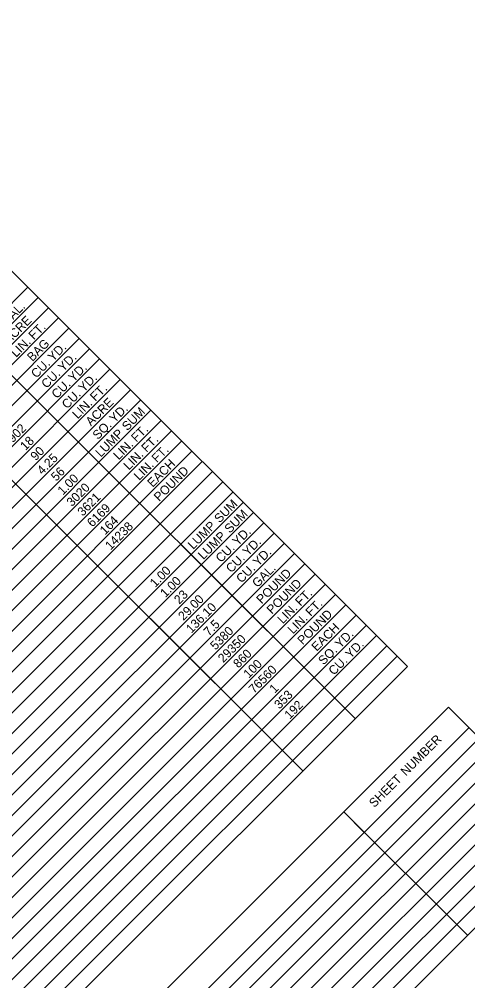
# Model space of a CAD drawing. Extents: x 1675667 to 1681231, y 227227 to 232694.
# Drawn here: x 1680479 to 1680780, y 231542 to 232189 of the extents above; entities that cross this region are included whole.
import ezdxf

# ---------------------------------------------------------------- set-up
doc = ezdxf.new("R2010")
doc.units = 0
doc.layers.add('Default', color=7, linetype='Continuous')

msp = doc.modelspace()

# ---------------------------------------------------------------- linework, layer by layer
at = {"layer": 'Default'}
for p, q in [((1680739.5, 231753.4), (1680174.44, 232318.32)), ((1680704.34, 231718.24), (1680139.29, 232283.16)), ((1680580.23, 231842.32), (1680139.29, 232283.16)), ((1680669.19, 231683.07), (1680104.13, 232247.99)), ((1680545.07, 231807.16), (1680124.81, 232227.31)), ((1680011.14, 231535.11), (1680484.38, 232008.46)), ((1680018.04, 231528.22), (1680491.27, 232001.57)), ((1680024.93, 231521.32), (1680498.17, 231994.67)), ((1680031.83, 231514.43), (1680505.06, 231987.78)), ((1680038.72, 231507.54), (1680511.96, 231980.89)), ((1680045.62, 231500.64), (1680518.85, 231973.99)), ((1680052.51, 231493.75), (1680525.75, 231967.1)), ((1680059.41, 231486.86), (1680532.65, 231960.21)), ((1680066.31, 231479.96), (1680539.54, 231953.31)), ((1680073.2, 231473.07), (1680546.44, 231946.42)), ((1680080.1, 231466.18), (1680553.33, 231939.53)), ((1680086.99, 231459.28), (1680560.23, 231932.63)), ((1680093.89, 231452.39), (1680567.12, 231925.74)), ((1680100.78, 231445.5), (1680574.02, 231918.85)), ((1680107.68, 231438.6), (1680580.91, 231911.95)), ((1680114.57, 231431.71), (1680587.81, 231905.06)), ((1680121.47, 231424.82), (1680594.7, 231898.17)), ((1680128.36, 231417.92), (1680601.6, 231891.27)), ((1680135.26, 231411.03), (1680608.49, 231884.38)), ((1680142.15, 231404.14), (1680615.39, 231877.49)), ((1680580.23, 231842.32), (1680615.39, 231877.49)), ((1680149.05, 231397.24), (1680622.28, 231870.59)), ((1680155.94, 231390.35), (1680629.18, 231863.7)), ((1680162.84, 231383.45), (1680636.07, 231856.81)), ((1680169.73, 231376.56), (1680642.97, 231849.91)), ((1680176.63, 231369.67), (1680649.86, 231843.02)), ((1680183.52, 231362.77), (1680656.76, 231836.13)), ((1680704.34, 231718.24), (1680587.13, 231835.43)), ((1680190.42, 231355.88), (1680663.65, 231829.23)), ((1680197.31, 231348.99), (1680670.55, 231822.34)), ((1680204.21, 231342.09), (1680677.44, 231815.45)), ((1680211.1, 231335.2), (1680684.34, 231808.55)), ((1680218, 231328.31), (1680691.23, 231801.66)), ((1680669.19, 231683.07), (1680551.97, 231800.26)), ((1680224.89, 231321.41), (1680698.13, 231794.77)), ((1680231.79, 231314.52), (1680705.02, 231787.87)), ((1680238.68, 231307.63), (1680711.92, 231780.98)), ((1680245.58, 231300.73), (1680718.81, 231774.08)), ((1680252.47, 231293.84), (1680725.71, 231767.19)), ((1680259.37, 231286.95), (1680732.6, 231760.3)), ((1680266.26, 231280.05), (1680739.5, 231753.4)), ((1680293.84, 231252.48), (1680767.08, 231725.83)), ((1680696.77, 231655.5), (1680767.08, 231725.83)), ((1680850.17, 231642.76), (1680767.08, 231725.83)), ((1680850.17, 231642.76), (1680767.08, 231725.83)), ((1680307.63, 231238.69), (1680780.87, 231712.04)), ((1680314.53, 231231.8), (1680787.77, 231705.15)), ((1680321.43, 231224.91), (1680794.66, 231698.26)), ((1680328.32, 231218.01), (1680801.56, 231691.36)), ((1680335.22, 231211.12), (1680808.45, 231684.47)), ((1680342.11, 231204.23), (1680815.35, 231677.58)), ((1680349.01, 231197.33), (1680822.24, 231670.68)), ((1680355.9, 231190.44), (1680829.14, 231663.79)), ((1680362.8, 231183.54), (1680836.03, 231656.9)), ((1680710.56, 231641.71), (1680696.77, 231655.5)), ((1680779.85, 231572.43), (1680696.77, 231655.5)), ((1680369.69, 231176.65), (1680842.93, 231650)), ((1680376.93, 231169.41), (1680850.17, 231642.76))]:
    msp.add_line(p, q, dxfattribs=at)

# ---------------------------------------------------------------- texts
for s, p in [(' GAL.', (1680468.56, 231980.55)), ('ACRE', (1680471.67, 231969.86)), (' FT.', (1680486.8, 231971.21)), ('LIN.', (1680476.45, 231960.86)), ('BAG', (1680487.46, 231958.08)), (' YD.', (1680499.77, 231956.6)), ('CU.', (1680490.08, 231946.91)), (' YD.', (1680506.66, 231949.71)), (' YD.', (1680513.56, 231942.81)), ('CU.', (1680496.97, 231940.01)), (' YD.', (1680520.45, 231935.92)), ('CU.', (1680503.87, 231933.12)), (' FT.', (1680528.17, 231929.85)), ('CU.', (1680510.76, 231926.23)), ('ACRE', (1680526.83, 231914.71)), ('LIN.', (1680517.83, 231919.5)), (' YD.', (1680541.14, 231915.24)), (' SUM', (1680549.61, 231909.92)), ('902', (1680474.28, 231903.52)), ('SQ.', (1680531.45, 231905.55)), (' FT.', (1680555.76, 231902.28)), ('18', (1680482.79, 231898.25)), ('LUMP', (1680533.4, 231893.71)), (' FT.', (1680562.65, 231895.39)), ('90', (1680489.7, 231891.37)), ('LIN.', (1680545.41, 231891.93)), (' FT.', (1680569.55, 231888.49)), ('4.25', (1680494.1, 231881.98)), ('LIN.', (1680552.3, 231885.03)), ('LIN.', (1680559.2, 231878.14)), ('EACH', (1680568.28, 231873.43)), ('56', (1680503.48, 231877.57)), ('1.00', (1680507.91, 231868.22)), ('POUND', (1680572.62, 231863.99)), ('3020', (1680513.99, 231860.5)), ('3621', (1680521.28, 231854.01)), ('6169', (1680527.76, 231846.7)), (' SUM', (1680611.67, 231847.88)), (' SUM', (1680618.56, 231840.99)), ('164', (1680536.32, 231841.47)), ('14238', (1680539.91, 231831.27)), ('LUMP', (1680595.46, 231831.67)), ('LUMP', (1680602.35, 231824.78)), (' YD.', (1680623.88, 231832.52)), (' YD.', (1680630.78, 231825.63)), ('CU.', (1680614.19, 231822.83)), (' YD.', (1680637.67, 231818.73)), ('CU.', (1680621.09, 231815.93)), ('1.00', (1680569.97, 231806.18)), ('CU.', (1680627.98, 231809.04)), ('GAL.', (1680638.73, 231806)), ('POUND', (1680641.58, 231795.06)), ('1.00', (1680576.87, 231799.28)), ('POUND', (1680648.47, 231788.16)), ('23', (1680586.22, 231794.85)), (' FT.', (1680666.08, 231791.98)), ('29.00', (1680589.01, 231783.85)), (' FT.', (1680672.97, 231785.09)), ('136.10', (1680594.26, 231775.31)), ('LIN.', (1680655.73, 231781.63)), ('POUND', (1680669.16, 231767.48)), ('7.5', (1680606.07, 231773.33)), ('LIN.', (1680662.62, 231774.74)), ('5380', (1680610.52, 231763.99)), ('EACH', (1680678.6, 231763.14)), ('29350', (1680615.76, 231755.45)), (' YD.', (1680692.83, 231763.59)), ('SQ.', (1680683.14, 231753.89)), (' YD.', (1680699.73, 231756.69)), ('860', (1680625.95, 231751.85)), ('CU.', (1680690.04, 231747)), ('100', (1680632.85, 231744.96)), ('76560', (1680636.45, 231734.77)), ('1', (1680650.34, 231734.87)), ('353', (1680653.53, 231724.27)), ('192', (1680660.44, 231717.4)), (' NUMBER', (1680736.95, 231677.66)), ('SHEET', (1680717.3, 231658.01))]:
    msp.add_text(s, height=6, rotation=45.00703, dxfattribs=at).set_placement(p)

doc.saveas('drawing.dxf')
